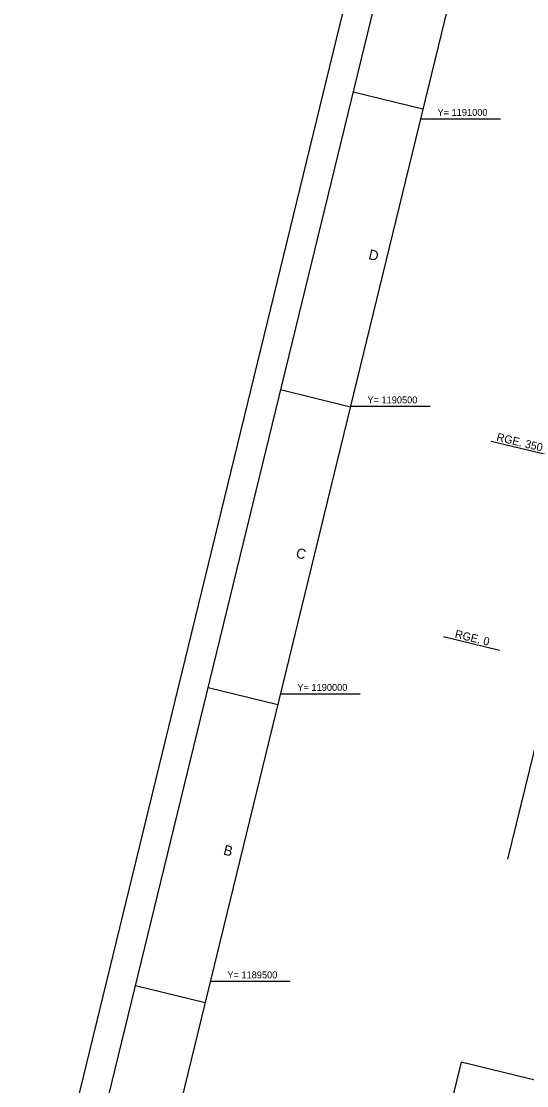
# Model space of a CAD drawing. Extents: x 412170 to 417250, y 1187847 to 1192192.
# Drawn here: x 412170 to 413049, y 1189318 to 1191169 of the extents above; entities that cross this region are included whole.
import ezdxf

# ---------------------------------------------------------------- set-up
doc = ezdxf.new("R2010")
doc.units = 0
for name, color, linetype in [('G-ANNO-NPLT', 7, 'Continuous'), ('G-ANNO-TTLB', 7, 'Continuous'), ('V-ALGN-TEXT', 7, 'Continuous'), ('V-ANNO-MATC', 7, 'Continuous'), ('V-TOPO-COOR-STAT', 7, 'Continuous')]:
    doc.layers.add(name, color=color, linetype=linetype)

msp = doc.modelspace()

# ---------------------------------------------------------------- linework, layer by layer
at = {"layer": 'G-ANNO-NPLT'}
msp.add_lwpolyline([(412975.1, 1192192.3), (417249.8, 1191149.8), (416444.2, 1187846.7), (412169.5, 1188889.2)], close=True, dxfattribs=at)
at = {"layer": 'G-ANNO-TTLB'}
for p, q in [((412747.2, 1191046.9), (412868.6, 1191017.3)), ((412620.8, 1190528.8), (412742.3, 1190499.2)), ((412494.5, 1190010.7), (412615.9, 1189981.1)), ((412368.1, 1189492.6), (412489.6, 1189462.9))]:
    msp.add_line(p, q, dxfattribs=at)
for points in [[(412229.9, 1188925.9), (416407.5, 1187907.1), (417189.3, 1191113.1), (413011.8, 1192131.9)], [(417128.9, 1191076.4), (413121.4, 1192053.7), (412363.2, 1188944.8), (416370.7, 1187967.5)]]:
    msp.add_lwpolyline(points, close=True, dxfattribs=at)
at = {"layer": 'V-ALGN-TEXT'}
for p, q in [((412987.4, 1190439.5), (413084.6, 1190415.8)), ((412904.5, 1190099.5), (413001.7, 1190075.8))]:
    msp.add_line(p, q, dxfattribs=at)
at = {"layer": 'V-ANNO-MATC'}
msp.add_line((413347.6, 1191072.2), (413015.9, 1189712), dxfattribs=at)
msp.add_lwpolyline([(414610.8, 1188950.5), (412934.8, 1189359.2), (412844.8, 1188990.3), (414520.8, 1188581.6)], close=True, dxfattribs=at)
at = {"layer": 'V-TOPO-COOR-STAT'}
for p, q in [((412864.4, 1191000), (413003.4, 1191000)), ((412742.5, 1190500), (412881.4, 1190500)), ((412620.5, 1190000), (412759.5, 1190000)), ((412498.6, 1189500), (412637.6, 1189500))]:
    msp.add_line(p, q, dxfattribs=at)

# ---------------------------------------------------------------- texts
at = {"layer": 'G-ANNO-TTLB'}
for s, p in [('D', (412772.6, 1190756.2)), ('C', (412646.2, 1190237.1)), ('B', (412520, 1189720.5))]:
    msp.add_text(s, height=17.5, rotation=346.2946, dxfattribs=at).set_placement(p)
at = {"layer": 'V-ALGN-TEXT'}
for s, p in [('RGE. 350', (412995.7, 1190440.4)), ('RGE. 0', (412923.2, 1190097.8))]:
    msp.add_text(s, height=13.92, rotation=346.2946, dxfattribs=at).set_placement(p)
at = {"layer": 'V-TOPO-COOR-STAT'}
for s, p in [('Y= 1191000', (412893.9, 1191005)), ('Y= 1190500', (412771.9, 1190505)), ('Y= 1190000', (412650, 1190005)), ('Y= 1189500', (412528.1, 1189505))]:
    msp.add_text(s, height=12, dxfattribs=at).set_placement(p)

doc.saveas('drawing.dxf')
